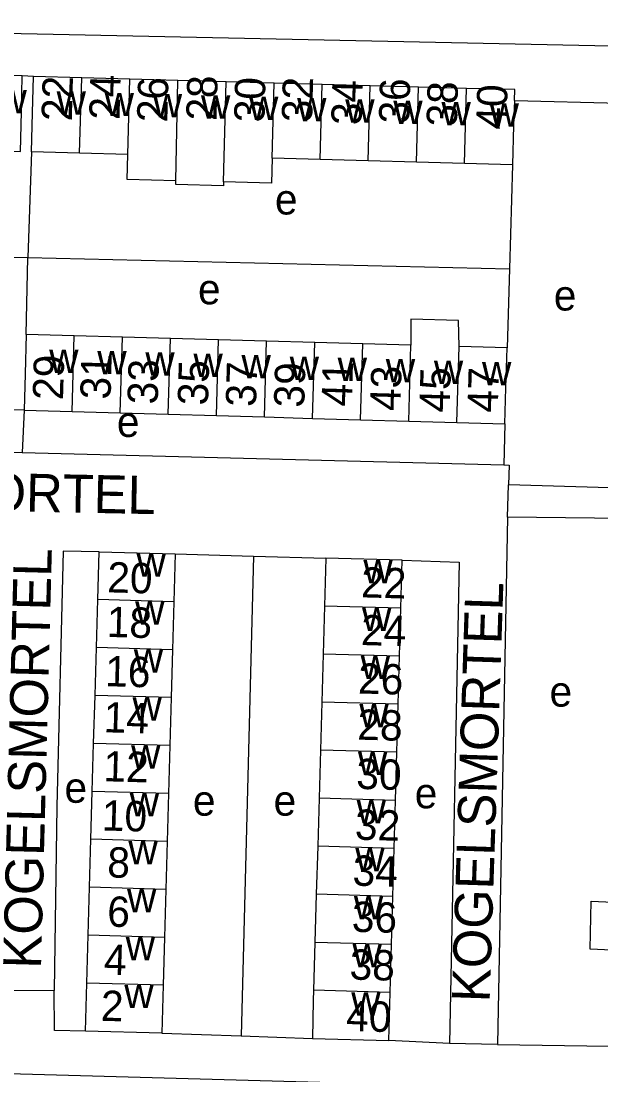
# Model space of a CAD drawing. Extents: x 161936 to 163647, y 386450 to 388633.
# Drawn here: x 162433.8 to 162510.2, y 388326.7 to 388465.5 of the extents above; entities that cross this region are included whole.
import ezdxf

# ---------------------------------------------------------------- set-up
doc = ezdxf.new("R2010")
doc.units = 0
for name, color, linetype in [('BLT_Basislijn', 7, 'Continuous'), ('BLT_Bebouwing', 7, 'Continuous'), ('BLT_Centroide', 7, 'Continuous'), ('BLT_Huisnummer', 7, 'Continuous'), ('BLT_Huisnummer_ tussenligend', 7, 'Continuous'), ('BLT_Onderverdeling_panden', 7, 'Continuous'), ('BLT_Straatnaam', 7, 'Continuous')]:
    doc.layers.add(name, color=color, linetype=linetype)

msp = doc.modelspace()

# ---------------------------------------------------------------- linework, layer by layer
at = {"layer": 'BLT_Basislijn'}
for p, q in [((162435.42, 388458.21), (162433.93, 388458.27)), ((162498.77, 388455.06), (162512.72, 388454.7)), ((162435.15, 388448.3), (162434.64, 388434.35)), ((162498.52, 388446.56), (162498.11, 388432.87)), ((162395.42, 388435.04), (162434.64, 388434.35)), ((162434.45, 388424.24), (162434.64, 388434.35)), ((162434.64, 388434.35), (162498.11, 388432.87)), ((162498.11, 388432.87), (162497.8, 388422.45)), ((162434.16, 388414.26), (162432.77, 388414.3)), ((162434.16, 388414.26), (162433.91, 388408.67)), ((162497.52, 388412.46), (162497.39, 388407.05)), ((162433.91, 388408.67), (162497.39, 388407.05)), ((162497.85, 388400.17), (162497.99, 388404.44)), ((162511.29, 388404.01), (162497.99, 388404.44)), ((162497.85, 388400.17), (162496.55, 388330.73)), ((162513.15, 388400), (162497.85, 388400.17)), ((162454.08, 388395.34), (162464.4, 388395.05)), ((162464.4, 388395.05), (162462.78, 388331.84)), ((162464.4, 388395.05), (162473.92, 388394.78)), ((162431.16, 388337.88), (162438.14, 388337.82)), ((162452.3, 388332.19), (162462.78, 388331.84)), ((162462.78, 388331.84), (162472.15, 388331.52)), ((162490.22, 388330.84), (162482.22, 388331.24)), ((162496.55, 388330.73), (162490.22, 388330.84)), ((162496.55, 388330.73), (162511.26, 388330.48))]:
    msp.add_line(p, q, dxfattribs=at)
for points in [[(162356.1, 388465.5), (162530.37, 388461.84), (162530.19, 388455.5), (162530.16, 388454.16)], [(162394.89, 388415.31), (162394.88, 388410.18), (162433.91, 388408.67)], [(162497.39, 388407.05), (162498.06, 388407.03), (162497.99, 388404.44)], [(162444.05, 388395.62), (162439.33, 388395.7), (162438.49, 388362.05), (162438.14, 388337.82)], [(162484, 388394.5), (162491.47, 388394.25), (162490.22, 388330.84)], [(162442.26, 388332.48), (162438.16, 388332.54), (162438.14, 388337.82)], [(162527.34, 388329.93), (162527.27, 388324.42), (162526.79, 388324.23), (162432.11, 388326.83), (162430.18, 388327.2), (162430.18, 388331.55), (162405.64, 388332.15), (162405.25, 388327.65), (162400.54, 388326.98), (162394.91, 388325.05), (162392.42, 388322.81), (162391.7, 388321.53), (162391.07, 388319.82)]]:
    msp.add_lwpolyline(points, dxfattribs=at)
at = {"layer": 'BLT_Bebouwing'}
for p, q in [((162433.93, 388458.27), (162427.61, 388458.42)), ((162441.76, 388458.04), (162435.42, 388458.21)), ((162448.09, 388457.86), (162441.76, 388458.04)), ((162454.43, 388457.69), (162448.09, 388457.86)), ((162460.77, 388457.51), (162454.43, 388457.69)), ((162467.11, 388457.34), (162460.77, 388457.51)), ((162473.44, 388457.17), (162467.11, 388457.34)), ((162479.78, 388456.99), (162473.44, 388457.17)), ((162486.12, 388456.82), (162479.78, 388456.99)), ((162492.46, 388456.64), (162486.12, 388456.82)), ((162441.48, 388448.12), (162435.15, 388448.3)), ((162447.82, 388447.95), (162441.48, 388448.12)), ((162473.17, 388447.26), (162466.84, 388447.43)), ((162479.51, 388447.08), (162473.17, 388447.26)), ((162485.85, 388446.91), (162479.51, 388447.08)), ((162492.19, 388446.74), (162485.85, 388446.91)), ((162498.52, 388446.56), (162492.19, 388446.74)), ((162440.78, 388424.06), (162434.45, 388424.24)), ((162447.12, 388423.88), (162440.78, 388424.06)), ((162453.45, 388423.7), (162447.12, 388423.88)), ((162459.79, 388423.52), (162453.45, 388423.7)), ((162466.12, 388423.34), (162459.79, 388423.52)), ((162472.46, 388423.17), (162466.12, 388423.34)), ((162478.8, 388422.99), (162472.46, 388423.17)), ((162485.13, 388422.8), (162478.8, 388422.99)), ((162497.8, 388422.45), (162491.47, 388422.63)), ((162434.16, 388414.26), (162440.5, 388414.08)), ((162440.5, 388414.08), (162446.83, 388413.9)), ((162446.83, 388413.9), (162453.17, 388413.72)), ((162453.17, 388413.72), (162459.51, 388413.54)), ((162459.51, 388413.54), (162465.84, 388413.36)), ((162465.84, 388413.36), (162472.18, 388413.18)), ((162472.18, 388413.18), (162478.51, 388413)), ((162478.51, 388413), (162484.85, 388412.82)), ((162484.85, 388412.82), (162491.19, 388412.64)), ((162491.19, 388412.64), (162497.52, 388412.46)), ((162443.87, 388389.31), (162444.05, 388395.62)), ((162444.05, 388395.62), (162454.08, 388395.34)), ((162454.08, 388395.34), (162453.9, 388389.03)), ((162473.92, 388394.78), (162473.74, 388388.46)), ((162484, 388394.5), (162473.92, 388394.78)), ((162483.82, 388388.18), (162484, 388394.5)), ((162443.69, 388383), (162443.87, 388389.31)), ((162453.9, 388389.03), (162453.72, 388382.71)), ((162473.74, 388388.46), (162473.57, 388382.14)), ((162483.64, 388381.85), (162483.82, 388388.18)), ((162443.51, 388376.68), (162443.69, 388383)), ((162453.72, 388382.71), (162453.55, 388376.4)), ((162473.57, 388382.14), (162473.39, 388375.81)), ((162483.46, 388375.53), (162483.64, 388381.85)), ((162443.33, 388370.37), (162443.51, 388376.68)), ((162453.55, 388376.4), (162453.37, 388370.08)), ((162473.39, 388375.81), (162473.21, 388369.48)), ((162483.29, 388369.2), (162483.46, 388375.53)), ((162443.15, 388364.05), (162443.33, 388370.37)), ((162453.37, 388370.08), (162453.19, 388363.77)), ((162473.21, 388369.48), (162473.03, 388363.16)), ((162483.11, 388362.87), (162483.29, 388369.2)), ((162442.98, 388357.74), (162443.15, 388364.05)), ((162453.19, 388363.77), (162453.01, 388357.45)), ((162473.03, 388363.16), (162472.85, 388356.83)), ((162482.93, 388356.54), (162483.11, 388362.87)), ((162442.8, 388351.42), (162442.98, 388357.74)), ((162453.01, 388357.45), (162452.84, 388351.14)), ((162472.85, 388356.83), (162472.67, 388350.5)), ((162482.75, 388350.22), (162482.93, 388356.54)), ((162442.62, 388345.11), (162442.8, 388351.42)), ((162452.84, 388351.14), (162452.66, 388344.82)), ((162472.67, 388350.5), (162472.49, 388344.17)), ((162482.57, 388343.89), (162482.75, 388350.22)), ((162442.44, 388338.79), (162442.62, 388345.11)), ((162452.66, 388344.82), (162452.48, 388338.51)), ((162472.49, 388344.17), (162472.31, 388337.85)), ((162482.39, 388337.56), (162482.57, 388343.89)), ((162442.26, 388332.48), (162442.44, 388338.79)), ((162452.48, 388338.51), (162452.3, 388332.19)), ((162482.22, 388331.24), (162482.39, 388337.56)), ((162452.3, 388332.19), (162442.26, 388332.48)), ((162472.15, 388331.52), (162482.22, 388331.24))]:
    msp.add_line(p, q, dxfattribs=at)
for points in [[(162427.36, 388448.46), (162433.69, 388448.31), (162433.82, 388453.54), (162433.93, 388458.27)], [(162435.15, 388448.3), (162435.28, 388453.4), (162435.42, 388458.21)], [(162498.77, 388455.06), (162498.81, 388456.47), (162492.46, 388456.64)], [(162498.77, 388455.06), (162498.67, 388451.73), (162498.52, 388446.56)], [(162454.15, 388444.47), (162447.76, 388444.64), (162447.82, 388447.95)], [(162466.84, 388447.43), (162466.75, 388444.17), (162460.45, 388444.34)], [(162460.45, 388444.34), (162460.44, 388443.82), (162454.14, 388443.99), (162454.15, 388444.47)], [(162491.47, 388422.63), (162491.41, 388426.06), (162485.11, 388426.24), (162485.13, 388422.8)], [(162434.45, 388424.24), (162434.3, 388419.03), (162434.16, 388414.26)], [(162497.52, 388412.46), (162497.65, 388417.19), (162497.8, 388422.45)], [(162511.61, 388343.12), (162508.73, 388343.28), (162508.9, 388349.57), (162511.78, 388349.45)], [(162472.31, 388337.85), (162472.27, 388336.52), (162472.15, 388331.52)]]:
    msp.add_lwpolyline(points, dxfattribs=at)
at = {"layer": 'BLT_Onderverdeling_panden'}
for p, q in [((162441.48, 388448.12), (162441.76, 388458.04)), ((162447.82, 388447.95), (162448.09, 388457.86)), ((162454.15, 388444.47), (162454.43, 388457.69)), ((162460.45, 388444.34), (162460.77, 388457.51)), ((162466.84, 388447.43), (162467.11, 388457.34)), ((162473.17, 388447.26), (162473.44, 388457.17)), ((162479.51, 388447.08), (162479.78, 388456.99)), ((162485.85, 388446.91), (162486.12, 388456.82)), ((162492.19, 388446.74), (162492.46, 388456.64)), ((162440.5, 388414.08), (162440.78, 388424.06)), ((162446.83, 388413.9), (162447.12, 388423.88)), ((162453.17, 388413.72), (162453.45, 388423.7)), ((162459.51, 388413.54), (162459.79, 388423.52)), ((162465.84, 388413.36), (162466.12, 388423.34)), ((162472.18, 388413.18), (162472.46, 388423.17)), ((162478.51, 388413), (162478.8, 388422.99)), ((162484.85, 388412.82), (162485.13, 388422.8)), ((162491.19, 388412.64), (162491.47, 388422.63)), ((162453.9, 388389.03), (162443.87, 388389.31)), ((162483.82, 388388.18), (162473.74, 388388.46)), ((162453.72, 388382.71), (162443.69, 388383)), ((162483.64, 388381.85), (162473.57, 388382.14)), ((162453.55, 388376.4), (162443.51, 388376.68)), ((162483.46, 388375.53), (162473.39, 388375.81)), ((162453.37, 388370.08), (162443.33, 388370.37)), ((162483.29, 388369.2), (162473.21, 388369.48)), ((162453.19, 388363.77), (162443.15, 388364.05)), ((162483.11, 388362.87), (162473.03, 388363.16)), ((162453.01, 388357.45), (162442.98, 388357.74)), ((162482.93, 388356.54), (162472.85, 388356.83)), ((162452.84, 388351.14), (162442.8, 388351.42)), ((162482.75, 388350.22), (162472.67, 388350.5)), ((162452.66, 388344.82), (162442.62, 388345.11)), ((162482.57, 388343.89), (162472.49, 388344.17)), ((162452.48, 388338.51), (162442.44, 388338.79)), ((162482.39, 388337.56), (162472.31, 388337.85))]:
    msp.add_line(p, q, dxfattribs=at)

# ---------------------------------------------------------------- texts
at = {"layer": 'BLT_Centroide'}
for s, p in [('w', (162430.66, 388453.36)), ('w', (162438.45, 388453.17)), ('w', (162444.78, 388452.98)), ('w', (162451.12, 388452.83)), ('w', (162457.47, 388452.64)), ('w', (162463.8, 388452.47)), ('w', (162470.14, 388452.3)), ('w', (162476.48, 388452.12)), ('w', (162482.81, 388451.95)), ('w', (162489.16, 388451.77)), ('w', (162495.5, 388451.61)), ('e', (162467.22, 388440.03)), ('e', (162457.08, 388428.2)), ('e', (162503.96, 388427.38)), ('w', (162437.47, 388419.16)), ('w', (162443.81, 388418.97)), ('w', (162450.14, 388418.81)), ('w', (162456.48, 388418.62)), ('w', (162462.81, 388418.44)), ('w', (162469.16, 388418.25)), ('w', (162475.48, 388418.09)), ('w', (162481.83, 388417.91)), ('w', (162488.16, 388417.72)), ('w', (162494.5, 388417.53)), ('e', (162446.39, 388410.73)), ('w', (162448.98, 388392.31)), ('w', (162478.87, 388391.47)), ('w', (162448.8, 388386)), ('w', (162478.7, 388385.16)), ('w', (162448.62, 388379.69)), ('w', (162478.52, 388378.84)), ('e', (162503.4, 388375.21)), ('w', (162448.45, 388373.38)), ('w', (162478.34, 388372.5)), ('w', (162448.26, 388367.06)), ('w', (162478.16, 388366.19)), ('e', (162439.49, 388362.55)), ('e', (162485.64, 388361.82)), ('w', (162448.09, 388360.75)), ('e', (162456.41, 388360.85)), ('e', (162467.04, 388360.85)), ('w', (162477.98, 388359.84)), ('w', (162447.91, 388354.44)), ('w', (162477.8, 388353.53)), ('w', (162447.73, 388348.12)), ('w', (162477.62, 388347.19)), ('w', (162447.55, 388341.81)), ('w', (162477.44, 388340.88)), ('w', (162447.37, 388335.5)), ('w', (162477.27, 388334.53))]:
    msp.add_text(s, height=4, dxfattribs=at).set_placement(p)
at = {"layer": 'BLT_Huisnummer'}
for s, rotation, p in [('22', 88.4278, (162440.45, 388452.27)), ('30', 88.4328, (162465.82, 388452.12)), ('26', 88.4273, (162453.03, 388452.13)), ('34', 88.4323, (162478.62, 388451.76)), ('40', 88.3371, (162497.71, 388451.16)), ('29', 88.3769, (162439.29, 388415.55)), ('33', 88.3765, (162451.77, 388414.98)), ('37', 88.3764, (162464.72, 388414.66)), ('41', 88.376, (162477.34, 388414.71)), ('47', 88.3769, (162496.57, 388413.9)), ('20', 358.391, (162445.09, 388390.27)), ('22', 358.3865, (162478.53, 388389.61)), ('26', 358.3865, (162478.13, 388376.95)), ('14', 358.391, (162444.61, 388371.84)), ('30', 358.3866, (162477.9, 388364.39)), ('10', 358.3911, (162444.37, 388358.91)), ('34', 358.3866, (162477.41, 388351.65)), ('6', 358.3911, (162445.08, 388346.25)), ('2', 358.3854, (162444.24, 388333.84)), ('40', 358.3958, (162476.56, 388332.51))]:
    msp.add_text(s, height=4, rotation=rotation, dxfattribs=at).set_placement(p)
at = {"layer": 'BLT_Huisnummer_ tussenligend'}
for s, rotation, p in [('24', 88.4278, (162446.73, 388452.45)), ('28', 88.4273, (162459.51, 388452.34)), ('32', 88.4328, (162472.1, 388452.14)), ('36', 88.4323, (162484.9, 388451.96)), ('38', 88.4323, (162491.18, 388451.57)), ('31', 88.3769, (162445.55, 388415.63)), ('35', 88.3765, (162458.39, 388414.85)), ('39', 88.3764, (162471.07, 388414.56)), ('43', 88.376, (162483.74, 388414.11)), ('45', 88.376, (162490.23, 388413.91)), ('18', 358.391, (162445.02, 388384.4)), ('24', 358.3865, (162478.52, 388383.33)), ('16', 358.391, (162444.81, 388377.91)), ('28', 358.3865, (162478.04, 388370.87)), ('12', 358.3911, (162444.58, 388365.39)), ('32', 358.3866, (162477.72, 388357.7)), ('8', 358.3911, (162445.09, 388352.73)), ('36', 358.3866, (162477.31, 388345.57)), ('4', 358.3854, (162444.64, 388339.92)), ('38', 358.3866, (162477.02, 388339.28))]:
    msp.add_text(s, height=4, rotation=rotation, dxfattribs=at).set_placement(p)
at = {"layer": 'BLT_Straatnaam'}
for height, rotation, p in [(5, 358.8506, (162396.12, 388401.67)), (5, 88.5095, (162436.39, 388340.66)), (4.9999, 88.1113, (162495.5, 388336.23))]:
    msp.add_text('KOGELSMORTEL', height=height, rotation=rotation, dxfattribs=at).set_placement(p)

doc.saveas('drawing.dxf')
